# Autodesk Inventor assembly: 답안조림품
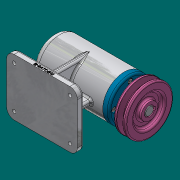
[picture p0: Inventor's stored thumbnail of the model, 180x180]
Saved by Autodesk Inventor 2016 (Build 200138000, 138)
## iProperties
Created: 2020-10
Part Number: 답안조림품
Material: 일반
Document SubType Name: Assembly
Designer: 605-15
Author: 605-15
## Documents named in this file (12)
- C:\Users\605-15\Desktop\701004V1002\답안조림품.iam
- C:\Users\605-15\Desktop\701004V1002\본체.ipt
- C:\Users\605-15\Desktop\701004V1002\베어링 6004.ipt
- C:\Users\605-15\Desktop\701004V1002\어댑터슬리브.ipt
- C:\Users\605-15\Desktop\701004V1002\베어링 51202.ipt
- C:\Users\605-15\Desktop\701004V1002\커버.ipt
- C:\Users\605-15\Desktop\701004V1002\오일 실.ipt
- C:\Users\605-15\Desktop\701004V1002\축.ipt
- C:\Users\605-15\Desktop\701004V1002\Ű 5 x 5 x 16.ipt
- C:\Users\605-15\Desktop\701004V1002\V벨트풀리.ipt
- C:\Users\605-15\Desktop\701004V1002\멈춤나사 M3.ipt
- C:\Users\605-15\Desktop\701004V1002\볼트 M4.ipt
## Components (2 placed, 2 different names)
1. Ű 5 x 5 x 16:1
2. V벨트풀리:1
